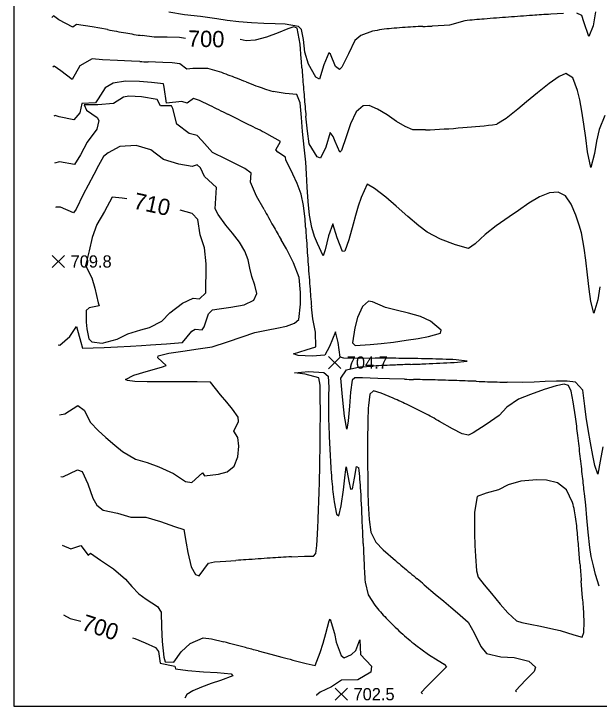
# Model space of a CAD drawing. Extents: x 2566079 to 2571326, y 424054 to 426896.
# Drawn here: x 2566079 to 2566796, y 424077 to 424925 of the extents above; entities that cross this region are included whole.
import ezdxf

# ---------------------------------------------------------------- set-up
doc = ezdxf.new("R2010")
doc.units = 0
for name, color, linetype in [('Contour_ADS_Label_Major', 7, 'Continuous'), ('Contour_ADS_Major', 7, 'Continuous'), ('Contour_ADS_Minor', 7, 'Continuous'), ('Contour_ADS_Spot_Elevation', 7, 'Continuous'), ('Contour_ADS_State_Plane_Border', 7, 'Continuous')]:
    doc.layers.add(name, color=color, linetype=linetype)

# ---------------------------------------------------------------- blocks, each defined once
blk = doc.blocks.new('S750')
at = {"layer": 'Contour_ADS_Spot_Elevation'}
for p, q in [((-0.5, 0.498), (0.5, -0.498)), ((-0.498, -0.5), (0.498, 0.5))]:
    blk.add_line(p, q, dxfattribs=at)

msp = doc.modelspace()

# ---------------------------------------------------------------- linework, layer by layer
at = {"layer": 'Contour_ADS_Major'}
for points in [[(2566193.96, 424905.69), (2566175.31, 424909.2), (2566156.2, 424912.12), (2566151.49, 424908.67), (2566134.44, 424917.57), (2566127.92, 424922.51), (2566125.79, 424920.5)], [(2566431.06, 424869.97), (2566429.61, 424888.07), (2566426.05, 424907.59), (2566422.09, 424909.1), (2566414.64, 424906.69), (2566402.83, 424901.8), (2566388.67, 424896.43), (2566374.88, 424892.71), (2566363.58, 424892.15), (2566356.27, 424893.56)], [(2566289.62, 424894.9), (2566282.15, 424895.97), (2566267, 424896.29), (2566250.93, 424896.68), (2566236.59, 424898.36)], [(2566802.65, 424800.73), (2566795.78, 424783.23), (2566792.72, 424769.07), (2566790.09, 424753.84), (2566785.67, 424736.76), (2566781.5, 424756.02), (2566779.33, 424773.1), (2566777.04, 424790.12), (2566774.64, 424805.86), (2566772.11, 424819.69), (2566769.46, 424831.11), (2566763.7, 424846.74), (2566755.16, 424851.84), (2566746.84, 424848.25), (2566734.54, 424839.72), (2566720.29, 424828.44), (2566706.84, 424817.24), (2566696.31, 424808.38), (2566681.98, 424796.95), (2566670.62, 424789.99)], [(2566583.36, 424782.98), (2566567.87, 424783.17), (2566558.45, 424787.15), (2566547.8, 424793.39), (2566536.11, 424801.21), (2566524.54, 424808.5), (2566514.47, 424812.84), (2566506.98, 424812.57), (2566498.52, 424805.05), (2566491.33, 424790.3), (2566486.23, 424774.43), (2566480.44, 424757.82), (2566478.48, 424755.63), (2566472.85, 424768.78), (2566470.31, 424774.88), (2566466.35, 424779.79), (2566461.22, 424761.8), (2566454.78, 424748.39), (2566450.56, 424749.99), (2566440.99, 424765.83), (2566438.63, 424781.42), (2566436.88, 424799.68)], [(2566217.7, 424698.52), (2566211.84, 424699.14), (2566199.68, 424700.34), (2566190.39, 424682.91), (2566180.98, 424666.84), (2566175.37, 424651.25), (2566171.34, 424634.86), (2566167.07, 424616.8), (2566174.76, 424601.7), (2566178.43, 424589.23), (2566182.41, 424571), (2566183.56, 424567.53), (2566171.66, 424564.82), (2566167.72, 424561.71), (2566167.81, 424547.23), (2566168.5, 424539.44), (2566171.13, 424527.02), (2566174.65, 424523.32), (2566187.6, 424521.55), (2566205.74, 424526.4), (2566218.79, 424533.21), (2566234.91, 424537.99), (2566245.2, 424540.8), (2566260.38, 424548.45), (2566270.39, 424559.04), (2566285.95, 424570.61), (2566298.68, 424576.91), (2566306.5, 424576.05), (2566314.42, 424583.15), (2566314.48, 424594.34), (2566314.61, 424605.56), (2566314.71, 424618.71), (2566312.76, 424638.5), (2566307.34, 424654.44), (2566304.52, 424673.16), (2566297.47, 424680.39), (2566282.86, 424684.43)], [(2566140.09, 424189.14), (2566148.24, 424184.53), (2566161.33, 424181.36)], [(2566224.75, 424160.8), (2566227.33, 424159.82), (2566240.09, 424154.62), (2566252.82, 424148.84), (2566256.59, 424144.11), (2566258.46, 424129.94), (2566276.5, 424125.89), (2566277.4, 424122.77), (2566292.46, 424120.82), (2566311.54, 424119.14), (2566328.34, 424118.29), (2566345.44, 424116.51), (2566347.19, 424114.23), (2566332.26, 424108.66), (2566320.86, 424104.83), (2566308.91, 424100.54), (2566298.31, 424095.98), (2566290.99, 424091.31), (2566288.54, 424087.06)]]:
    msp.add_lwpolyline(points, dxfattribs=at)
for centre, radius, start, end in [((2566576.89, 426961.56), 2091.23, 259.44887, 260.06836), ((2566353.41, 425682.02), 792.32, 260.02836, 261.52146), ((2562461.52, 424563.99), 3981.31, 4.24755, 4.40775), ((2569536.34, 425088.22), 3112.9, 184.2252, 184.43009), ((2569780.68, 425112.78), 3358.41, 184.52594, 184.94741), ((2570024.51, 425132.52), 3603.03, 184.92562, 185.30033), ((2566560.26, 425535.57), 752.94, 271.75825, 275.22988), ((2566591.92, 425358.39), 573.82, 273.69357, 277.88257)]:
    msp.add_arc(centre, radius, start, end, dxfattribs=at)
at = {"layer": 'Contour_ADS_Minor'}
for points in [[(2566518.37, 424903.71), (2566503.97, 424898.55), (2566496.75, 424892.42), (2566488.81, 424876.19), (2566480.69, 424859.68), (2566477.86, 424856.7), (2566473.23, 424860.72), (2566466.91, 424875.81), (2566464.81, 424877.43), (2566458.97, 424862.71), (2566453.35, 424845.1), (2566449.05, 424847.33), (2566440.06, 424863.55), (2566435.54, 424878.28), (2566433.75, 424893.66), (2566431.41, 424905.78), (2566427.64, 424909.64), (2566411.29, 424912.55), (2566399.23, 424912.86), (2566385.19, 424913.27), (2566370.04, 424914), (2566354.75, 424915.21), (2566340.3, 424916.92), (2566327.72, 424918.78), (2566307.96, 424921.78), (2566288.36, 424923.92), (2566269.23, 424926.96)], [(2566752.23, 424925.63), (2566736.54, 424924.63)], [(2566791.17, 424927.69), (2566788.56, 424910.25), (2566783.01, 424897.3), (2566777.04, 424915.17), (2566774.42, 424923.13), (2566768.42, 424926.01)], [(2566631.48, 424916.51), (2566612.73, 424911.38), (2566605.92, 424910.8), (2566591.5, 424910.12)], [(2566233.4, 424866.69), (2566223.25, 424867.14), (2566206.03, 424867.89), (2566187.81, 424868.88), (2566175.1, 424869.77), (2566160.07, 424861.18), (2566150.73, 424844.72), (2566137.03, 424855.08), (2566128.71, 424860.78), (2566126.98, 424859.64)], [(2566331.23, 424854), (2566316.96, 424858.12), (2566298.47, 424858.24), (2566291.03, 424857.27), (2566282.69, 424863.72), (2566273.11, 424865.05), (2566261.54, 424865.49), (2566243.55, 424866.24)], [(2566319.25, 424812.76), (2566306.41, 424818.81), (2566299.31, 424821.26), (2566291.33, 424815.56), (2566285.14, 424817.82), (2566266.02, 424815.82), (2566263.47, 424835.15), (2566262.55, 424839.16), (2566247.65, 424840.88), (2566233.17, 424842.1), (2566216.18, 424842.42), (2566201.01, 424840.22), (2566190.98, 424834.59), (2566182.35, 424821.02), (2566179.28, 424816.18), (2566162.69, 424815.15), (2566160.21, 424803.7), (2566152.72, 424795.06), (2566134.95, 424798.92), (2566130.06, 424800.57), (2566128.15, 424799.92)], [(2566796.68, 424590.65), (2566794.04, 424574.7), (2566789.41, 424558.61), (2566785.66, 424572.57), (2566783.76, 424587.75), (2566781.66, 424605.49), (2566779.51, 424623.19), (2566777.56, 424638.14), (2566774, 424656.86), (2566771.32, 424666.16), (2566767.3, 424678.63), (2566761.74, 424691.79), (2566754.51, 424702.02), (2566745.55, 424706.52), (2566734.97, 424705.71), (2566722.95, 424700.8), (2566709.85, 424693.1), (2566696.9, 424684.34), (2566685.51, 424676.29), (2566669.6, 424665.44), (2566656.33, 424654.67), (2566644.2, 424643.5), (2566636.02, 424637.77), (2566619.96, 424641.96), (2566601.57, 424649.04), (2566585.35, 424657.47), (2566575.11, 424665.22), (2566561.72, 424676.72), (2566547.29, 424689.61), (2566534.71, 424700.71), (2566520.98, 424711.19), (2566511.71, 424716.28), (2566504.32, 424700.09), (2566500.98, 424689.43), (2566497.62, 424678.14), (2566494.64, 424667.48), (2566489.51, 424648.32), (2566484.44, 424634.37), (2566481.52, 424634.13), (2566475, 424650.56), (2566469.73, 424667.88), (2566464.69, 424653.1), (2566460.47, 424636.02), (2566457.99, 424628.59), (2566450.94, 424643.85), (2566447.28, 424652.16), (2566443.89, 424663.5), (2566441.38, 424678.32), (2566439.66, 424695.32), (2566438.47, 424712.79), (2566437.54, 424729.15), (2566436.69, 424743.34), (2566434.54, 424761.8), (2566432.65, 424781.12), (2566431.54, 424798.13), (2566430.01, 424816.02), (2566425.86, 424826.29), (2566411.58, 424827.4), (2566396.74, 424830.06)], [(2566385.6, 424685.27), (2566376.44, 424701.78), (2566369.08, 424718.9), (2566369.97, 424729.75), (2566362.09, 424735.43), (2566351.57, 424740.96), (2566339.15, 424747.17), (2566322.65, 424755.36), (2566309.48, 424770.04), (2566303.77, 424776.17), (2566293.87, 424778.36), (2566278.92, 424789.78), (2566274.08, 424808.98), (2566272.36, 424812.41), (2566259.02, 424812.57), (2566254.77, 424820.22), (2566235.64, 424823.29), (2566220.07, 424824.09), (2566213.48, 424823.15), (2566201.36, 424815.07), (2566182.31, 424813.53), (2566165.46, 424813.48), (2566168.07, 424807.08), (2566181.19, 424798.15), (2566183.16, 424794.34), (2566181.06, 424783.85), (2566169.2, 424767.83), (2566160.9, 424752.17), (2566153.44, 424740.51), (2566135.02, 424743.63), (2566129.28, 424742.35)], [(2566435.8, 424673.37), (2566434.06, 424690.14), (2566431.08, 424704.04), (2566426.26, 424717.16), (2566420.74, 424728.74), (2566412.46, 424746.43), (2566411.95, 424749.7), (2566402.39, 424755.57), (2566400.15, 424758.51), (2566405.76, 424768.52), (2566388.85, 424778.23)], [(2566133.63, 424519.77), (2566135.44, 424519.11), (2566147.95, 424529.84), (2566156.08, 424542.01), (2566161.31, 424523.02), (2566163.48, 424515.66), (2566176.45, 424515.91), (2566189.7, 424516.49), (2566206.1, 424517.23), (2566222.26, 424518.04), (2566235.61, 424518.84), (2566246.64, 424519.6), (2566266.38, 424520.97), (2566285.78, 424522.68), (2566297.24, 424536.26), (2566301.33, 424538.87), (2566309.66, 424538.03), (2566312.42, 424541.63), (2566317.8, 424557.55), (2566322.51, 424562.53), (2566330.7, 424563.84), (2566345.06, 424565.64), (2566361.15, 424568.82), (2566373.09, 424574.25), (2566376.67, 424582.46), (2566374.4, 424592.54), (2566370.47, 424603.23), (2566368.01, 424613.54), (2566365.96, 424623.72), (2566362.21, 424634.27), (2566355.35, 424645.46), (2566346.86, 424656.47), (2566338.89, 424666.24), (2566329.54, 424679.43), (2566325.95, 424686.05), (2566327.17, 424705.91), (2566327.23, 424712.33), (2566312.78, 424725.74), (2566307.63, 424736.31), (2566303.88, 424739.98), (2566297.6, 424738.19), (2566281.1, 424740.99), (2566262.6, 424746.62), (2566247.13, 424758.5), (2566229.08, 424763.9), (2566209.21, 424762.77), (2566194.92, 424754.62), (2566189.26, 424750.26), (2566182.95, 424739.33), (2566177.05, 424728.1), (2566170.26, 424715.19), (2566164.27, 424703.89), (2566155.64, 424686), (2566152.5, 424681.42), (2566136.56, 424688.07), (2566131.07, 424688.39), (2566130.34, 424687.96)], [(2566135.31, 424433.94), (2566141.57, 424435.28), (2566157.65, 424445.26), (2566165.33, 424439.47), (2566173.11, 424424.33), (2566182.5, 424414.57), (2566191.93, 424406.16), (2566202.77, 424396.88), (2566212.37, 424389.04), (2566228.08, 424379.77), (2566242.36, 424375.52), (2566256.85, 424370.14), (2566274.57, 424361.87), (2566289.37, 424352.4), (2566297, 424351.13), (2566310.27, 424363.05), (2566312.87, 424359.31), (2566329.76, 424361.09), (2566340.32, 424364.2), (2566349.08, 424371.12), (2566353.59, 424382.61), (2566354.54, 424395.67), (2566353.41, 424406.34), (2566348.78, 424413.86), (2566354.29, 424425.65), (2566353.98, 424431.1), (2566347.1, 424440.78), (2566340.02, 424449.26), (2566332.19, 424458.56), (2566319.99, 424474.12), (2566303.73, 424474.53), (2566284.06, 424474.47), (2566274.83, 424474.35), (2566259.78, 424474.31), (2566242.43, 424474.48), (2566227.46, 424474.95), (2566218.64, 424475.85), (2566216.09, 424477.32), (2566226.38, 424482.35), (2566244.13, 424488.01), (2566259.91, 424492.28), (2566265.86, 424494.38), (2566255.38, 424503.84), (2566255.82, 424506.19), (2566269.04, 424509.54), (2566286.15, 424511.91), (2566304.96, 424514.63), (2566322.11, 424517.33), (2566340.69, 424523.3), (2566358.86, 424529.46), (2566374.5, 424534.65), (2566390.84, 424538.19), (2566401.28, 424539.98), (2566413.04, 424542.6), (2566422.84, 424546.15), (2566428.25, 424550.62), (2566430.3, 424569.53), (2566430.26, 424583.88), (2566428.59, 424602.08), (2566421.5, 424620.13), (2566413.22, 424637.24), (2566406.59, 424648.18)], [(2566521.79, 424503.25), (2566502.12, 424503.12), (2566483.15, 424503.19), (2566478.68, 424504.68), (2566476.18, 424522.52), (2566473, 424535.46), (2566465.88, 424517.46), (2566460.14, 424507.08), (2566444.51, 424505.87), (2566427.41, 424506.75), (2566421.71, 424508.49), (2566437.04, 424513.39), (2566449.02, 424517.27), (2566448.69, 424535.34), (2566445.32, 424551.55), (2566443.75, 424566.15)], [(2566618.2, 424498.15), (2566634.18, 424499.83), (2566620.69, 424501.31)], [(2566557.59, 424477.47), (2566539.29, 424477.91), (2566524.71, 424478.39), (2566505.93, 424479.24), (2566496.85, 424479.35), (2566493.39, 424476.55), (2566491.59, 424461.72), (2566490.22, 424444.38), (2566488.63, 424426.5), (2566486.98, 424416.36), (2566483.96, 424432.44), (2566482.6, 424447.77), (2566481.38, 424460.26), (2566479.73, 424478.63), (2566486.6, 424489.2), (2566502.73, 424492.68), (2566519.37, 424493.72)], [(2566454.43, 424456.49), (2566454.13, 424470.06), (2566452.85, 424479.18), (2566436.12, 424483.82), (2566422.92, 424485.16), (2566440.21, 424487.01), (2566458.96, 424485.64), (2566464.17, 424481.37), (2566465.07, 424467.58), (2566464.55, 424457.1), (2566464.44, 424439.42)], [(2566766.85, 424431.32), (2566764.13, 424449.95), (2566761.39, 424463.1), (2566758.22, 424469.93), (2566752.87, 424471.49), (2566743.32, 424469.28), (2566728.55, 424464.75), (2566711.71, 424458.98), (2566696.99, 424452.99), (2566682.65, 424443.32), (2566673.36, 424433.23), (2566657.67, 424422.26), (2566641.58, 424411.72), (2566635.68, 424408.94), (2566628.3, 424410.8), (2566616.35, 424416.8), (2566600.55, 424425.8)], [(2566800.42, 424394.79), (2566797.18, 424376.98), (2566794.12, 424361.11), (2566790.57, 424371.96), (2566788.1, 424384.26), (2566785.16, 424399.63), (2566782.32, 424415.86), (2566780.05, 424431.03), (2566778.32, 424444.43), (2566775.67, 424464.23), (2566766.95, 424473.93), (2566756.73, 424475.34), (2566743.65, 424475.26), (2566729.76, 424474.56), (2566716.33, 424473.96), (2566701.6, 424473.7), (2566683.05, 424473.88)], [(2566543.72, 424454.26), (2566528.89, 424460.45), (2566519.73, 424463.14), (2566515.14, 424459.28), (2566513.26, 424445.42)], [(2566471.24, 424327.47), (2566474.13, 424312.32), (2566477.16, 424310.16), (2566480.14, 424322.43), (2566482.81, 424342.22), (2566484.89, 424360.53), (2566486.21, 424370.11), (2566489.52, 424352.61), (2566491.4, 424343.07), (2566493.67, 424343.15), (2566496.23, 424356.52), (2566498.93, 424370.69), (2566501.58, 424369.09)], [(2566136.78, 424358.49), (2566139.42, 424357.78), (2566157.06, 424366.46), (2566162.75, 424364.37), (2566169.69, 424349.31), (2566175.96, 424331.9), (2566181.1, 424323.13), (2566188.75, 424317.2), (2566206.27, 424313.6), (2566222.59, 424308.68), (2566241.03, 424308.48), (2566259.02, 424303.28), (2566276.16, 424297.31), (2566287.24, 424293.52), (2566290.4, 424276.76), (2566292.43, 424265.45), (2566296.3, 424247.94), (2566301.7, 424238.35), (2566306.21, 424236.84), (2566317.66, 424252.05), (2566324.79, 424253.72), (2566338.66, 424254.69), (2566351.06, 424255.55)], [(2566763.33, 424326.59), (2566756.02, 424342.09), (2566744.69, 424350.66), (2566731.55, 424353.92), (2566719.6, 424354.36), (2566699.93, 424352.62), (2566684.45, 424348.09), (2566672.5, 424342.14), (2566657.56, 424338.05), (2566646.47, 424333.73), (2566643.08, 424314.55), (2566643.06, 424302.31), (2566643.3, 424288.43), (2566643.73, 424274.08), (2566644.29, 424260.76), (2566645.61, 424243), (2566647.52, 424235.19), (2566654.88, 424225.81), (2566663.96, 424214.92), (2566674.67, 424202.19), (2566684.02, 424191.22), (2566694.64, 424181.49), (2566701.01, 424179.67), (2566701.01, 424179.67)], [(2566512.77, 424339.1), (2566513.17, 424325.15), (2566514.41, 424305.73), (2566516.46, 424290.35), (2566522.52, 424277.92), (2566531.52, 424268.72), (2566546.45, 424255.5)], [(2566795.92, 424223.93), (2566791.45, 424238.32), (2566788.69, 424248.94), (2566786.12, 424260.49), (2566784.28, 424271.58), (2566782.31, 424290.01), (2566780.86, 424307.63), (2566779.35, 424323.17), (2566777.8, 424337.55)], [(2566419.02, 424259.99), (2566435.21, 424260.72), (2566446.3, 424260.9), (2566448.94, 424263.89), (2566450.14, 424274.04), (2566451, 424287.8)], [(2566138.43, 424274.37), (2566148.96, 424269.82), (2566161.34, 424273.86), (2566170.36, 424261.96), (2566173.06, 424264.63), (2566185.25, 424255.8), (2566201.4, 424245.38), (2566215.88, 424232.75), (2566223.73, 424223.63), (2566232.42, 424214.82), (2566241.2, 424208.1), (2566255.01, 424199.19), (2566259.52, 424192.36), (2566260.09, 424173.69), (2566260.83, 424156.31), (2566262.92, 424137.31), (2566264.52, 424131.47), (2566275.25, 424131.15), (2566283.98, 424143.49), (2566295.16, 424153.99), (2566311.19, 424160.64), (2566321.15, 424159.64), (2566336.53, 424155.76)], [(2566509.39, 424229.03), (2566512.97, 424213.34), (2566521.07, 424200.65)], [(2566581.71, 424225.85), (2566595.18, 424214.42), (2566605.52, 424205.56), (2566614.21, 424198.2), (2566622.41, 424191.49), (2566635.34, 424180.13), (2566642.92, 424166.83), (2566650.91, 424150.34), (2566657.79, 424141.4), (2566675.3, 424137.55), (2566691.79, 424136.83), (2566709.85, 424132.38), (2566717.8, 424124.72), (2566716.37, 424119.74), (2566706.21, 424109.37), (2566693.27, 424095.72), (2566694.76, 424094.45)], [(2566775.62, 424209.58), (2566774.78, 424220.15), (2566773.93, 424230.72)], [(2566701.01, 424179.67), (2566711.26, 424177.57), (2566723.96, 424175.07), (2566736.82, 424172.42), (2566747.95, 424169.81), (2566764.66, 424164.28), (2566774.9, 424161.57), (2566777.23, 424167.15), (2566777.55, 424180.32), (2566776.47, 424199.01)], [(2566420.82, 424133.59), (2566436.99, 424129.34), (2566448.33, 424126.78), (2566454.4, 424142.75), (2566457.85, 424154.36), (2566461.05, 424165.96), (2566465.17, 424181.6), (2566466.61, 424183.69), (2566471.66, 424165.92), (2566473.97, 424155.61), (2566479.92, 424139.07), (2566483.53, 424136.48), (2566492.55, 424140.37), (2566497.96, 424145.24), (2566502.72, 424158.36), (2566503.85, 424140.5), (2566517.28, 424125.92), (2566516.16, 424118.72), (2566500.2, 424109.28), (2566480.32, 424108.74), (2566468.04, 424100.93), (2566454.12, 424094.44), (2566449.76, 424090.69), (2566449.74, 424089.99)], [(2566571.28, 424151.77), (2566586.88, 424140.54), (2566598.76, 424133.19), (2566606.22, 424128.42), (2566609.01, 424125.1), (2566595.1, 424111.47), (2566584.46, 424100.95), (2566577.98, 424093.91), (2566579.71, 424092.35)], [(2566378.44, 424144.76), (2566393.94, 424140.68), (2566407.38, 424137.13)]]:
    msp.add_lwpolyline(points, dxfattribs=at)
msp.add_lwpolyline([(2566577.1, 424554.37), (2566562.39, 424558.64), (2566547.34, 424562.08), (2566534.24, 424565.47), (2566518.29, 424572.23), (2566513.57, 424573.12), (2566506.23, 424566.66), (2566500.17, 424553.07), (2566496.74, 424540.37), (2566493.9, 424522.3), (2566497.02, 424518.96), (2566515.57, 424519.93), (2566528.89, 424521.25), (2566544.04, 424523.04), (2566559.6, 424525.21), (2566574.31, 424527.54), (2566586.94, 424529.75), (2566601.79, 424534.13), (2566602.54, 424537.68), (2566589.42, 424548.83), (2566577.1, 424554.37)], close=True, dxfattribs=at)
for centre, radius, start, end in [((2566923.25, 421626.18), 3303.44, 94.13554, 94.65601), ((2567418.82, 414775.41), 10172.12, 93.972742, 94.136836), ((2567373.3, 415534.23), 9411.97, 93.879286, 94.016339), ((2566723.66, 424058.62), 862.83, 94.55761, 96.13299), ((2566562.01, 424686.85), 221.21, 95.30422, 101.37776), ((2566600.8, 424279.63), 630.27, 92.95817, 95.39292), ((2566615.83, 423994.09), 916.21, 92.2478, 92.97522), ((2565969.42, 438409.85), 13514.06, 272.589117, 272.638392), ((2566580.42, 432579.23), 7720.34, 267.423756, 267.499156), ((2565768.49, 423329.21), 1625.32, 68.95821, 69.74293), ((2565271.82, 422030.49), 3015.77, 68.77095, 69.01045), ((2566545.8, 425295.88), 489.36, 248.16853, 249.64559), ((2566483.76, 425128.02), 310.41, 249.60582, 253.71944), ((2565020.75, 422130.02), 2980.46, 63.70042, 64.17208), ((2564159.09, 420372.81), 4937.57, 63.43856, 63.77111), ((2565114.72, 422272.27), 2811.27, 63.04931, 63.5487), ((2569663.53, 426507.64), 3750.45, 209.07194, 209.41686), ((2567644.45, 425368.7), 1432.29, 209.40078, 210.20246), ((2565897.73, 424631.71), 539.68, 3.23518, 4.42692), ((2577238.08, 425380.51), 10825.39, 183.804786, 183.864144), ((2574265.91, 425178.83), 7846.38, 183.857389, 184.070758), ((2570458.32, 424909.84), 4029.3, 184.0989, 184.53526), ((2568467.21, 424749.82), 2031.78, 184.47681, 185.18659), ((2566525.18, 422221.93), 2281.32, 89.35955, 90.08514), ((2566527.24, 422177.67), 2325.56, 88.50829, 89.42249), ((2566393.33, 428929.41), 4437.03, 272.21699, 272.45763), ((2566481.61, 426940.1), 2445.77, 272.38964, 273.20141), ((2566562.55, 423287.9), 1214.8, 87.25689, 88.81004), ((2566730.84, 420078.43), 4420.35, 92.39184, 92.74203), ((2566868.67, 416930.28), 7571.52, 92.298822, 92.439769), ((2566822.78, 436273.89), 11799.4, 268.712175, 268.765117), ((2566447.62, 418740.27), 5738.23, 88.684214, 88.793075), ((2566459.68, 419466.65), 5011.77, 88.34534, 88.63136), ((2566094.59, 408340.59), 16143.79, 88.092919, 88.190322), ((2565716.51, 396565.38), 27925.07, 88.093675, 88.121636), ((2566791.15, 428590.1), 4117.68, 267.97217, 268.16194), ((2566743.19, 427133.98), 2660.78, 268.1885, 268.70485), ((2564563.27, 424437.64), 1891.25, 359.8823, 0.57123), ((2566304.49, 423901.38), 602.42, 64.65872, 66.60192), ((2567184.99, 424412.63), 672.53, 177.20536, 179.37635), ((2566331.66, 423957.14), 540.4, 62.39337, 64.73211), ((2567492.7, 424453.31), 1028.36, 180.77417, 182.23726), ((2563399.13, 424435.58), 3055.39, 359.41263, 359.96565), ((2566095.5, 423533.98), 1024.9, 60.47678, 61.65661), ((2564495.37, 424138.04), 2290.33, 6.78176, 7.35701), ((2568438.6, 424393.25), 1926.28, 179.20577, 180.13144), ((2567856.86, 424463.52), 1392.64, 182.07204, 183.34354), ((2563260.23, 424435.81), 3194.28, 358.84785, 359.4341), ((2561030.01, 423722.67), 5780.5, 6.561131, 6.813919), ((2569373.06, 424391.15), 2860.74, 180.04653, 180.62637), ((2567559.97, 424442.37), 1095.03, 183.14488, 184.72988), ((2558499.7, 423426.18), 8328.11, 6.426803, 6.598461), ((2563360.7, 424433.65), 3093.8, 358.25012, 358.85035), ((2566018.68, 424313.2), 486.12, 3.25362, 6.60198), ((2566976.88, 424392.71), 509.84, 184.57124, 187.35224), ((2568621.83, 424377.91), 2109.42, 180.48975, 181.05423), ((2558129.88, 423389.72), 8699.69, 6.323822, 6.392806), ((2561738.54, 423781.83), 5069.81, 6.29302, 6.41151), ((2563627.74, 424425.17), 2826.62, 357.66936, 358.25676), ((2563392.46, 424168.03), 3116.35, 2.37737, 3.1779), ((2566615.36, 424286.56), 153.29, 7.37513, 15.13643), ((2564672.16, 424379.96), 1781.22, 357.03416, 357.75608), ((2566105.87, 424227.38), 666.19, 4.87865, 6.79801), ((2561237.79, 424076.46), 5272.97, 2.17432, 2.40029), ((2563244.49, 423983.31), 3537.96, 4.52422, 4.87602), ((2568309.93, 424339), 1804.05, 181.98458, 182.64509), ((2566911.07, 416305.32), 7969.94, 93.726922, 93.939833), ((2566584.43, 421340.67), 2924, 93.24285, 93.75347), ((2560818.12, 423788.72), 5972.12, 4.4476, 4.549128), ((2567153.96, 412900.67), 11383.23, 93.982086, 94.044653), ((2567473.51, 424299.82), 966.71, 182.61374, 184.19966), ((2568358.25, 426380.92), 2792.85, 229.55442, 230.03846), ((2589908.64, 426066.74), 23207.45, 184.4853, 184.511428), ((2569538.3, 427786.91), 4628.43, 230.02043, 230.15954), ((2564697.84, 421982.32), 2929.57, 49.98009, 50.19988), ((2589953.33, 426078.11), 23252.91, 184.530694, 184.556822), ((2565885.72, 424132.7), 893.21, 4.25751, 4.93773), ((2566698.06, 424345.02), 228.4, 219.20497, 224.53275), ((2566800.35, 424438.49), 366.91, 223.73373, 227.63039), ((2566770.49, 424401.86), 319.73, 227.16068, 231.46057), ((2563767.65, 414294.1), 10190.76, 75.245864, 75.399417), ((2561817.12, 406858.85), 17877.59, 75.218025, 75.269361), ((2572393.83, 446838.06), 23477.01, 255.226889, 255.260808)]:
    msp.add_arc(centre, radius, start, end, dxfattribs=at)
at = {"layer": 'Contour_ADS_State_Plane_Border'}
msp.add_lwpolyline([(2566079.33, 424077.11), (2571302.93, 424077.11), (2571302.93, 426873.74), (2566079.33, 426873.74), (2566079.33, 424077.11)], close=True, dxfattribs=at)

# ---------------------------------------------------------------- block references
at = {"layer": 'Contour_ADS_Spot_Elevation', "xscale": 15, "yscale": 15}
for p in [(2566133.84, 424621.77), (2566471.97, 424497.94), (2566480.17, 424091.77)]:
    msp.add_blockref('S750', p, dxfattribs=at)

# ---------------------------------------------------------------- texts
at = {"layer": 'Contour_ADS_Label_Major'}
for s, rotation, p in [('700', 358.85277, (2566292.24, 424884.84)), ('710', 347.79266, (2566224.65, 424686.78)), ('700', 342.03787, (2566160.93, 424170.97))]:
    msp.add_text(s, height=20, rotation=rotation, dxfattribs=at).set_placement(p)
at = {"layer": 'Contour_ADS_Spot_Elevation'}
for s, p in [('709.8', (2566148.84, 424614.27)), ('704.7', (2566486.97, 424490.44)), ('702.5', (2566495.17, 424084.27))]:
    msp.add_text(s, height=15, dxfattribs=at).set_placement(p)

doc.saveas('drawing.dxf')
